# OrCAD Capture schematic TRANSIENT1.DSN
size A
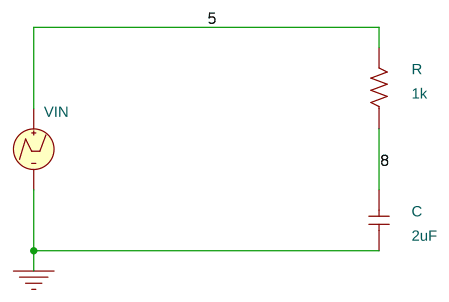
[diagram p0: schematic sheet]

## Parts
C  2uF  [RAD/CK05]
R  1k  [AX/RC05]
VIN  VPWL

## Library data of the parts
C = C
R = R
VIN = VPWL: PSpiceTemplate: V^@REFDES %+ %- ?DC|DC @DC| ?AC|AC @AC|\n+PWL @T1 @V1 @T2 @V2 #T3/@T3 @V3/ #T4/@T4 @V4/ #T5/@T5 @V5/ #T6/@T6 @V6/ #T7/@T7 @V7/ #T8/@T8 @V8/ #T9/@T9 @V9/ #T10/@T10 @V10/; T1: 0; T2: 1m; T3: 2m; T4: 3m; T5: 4m; T6: 5m; T7: 6m; V1: 0; V2: 1; V3: 0; V4: 1; V5: 0; V6: 1; V7: 0

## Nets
0: C.1 VIN.2(-)
5: R.2 VIN.1(+)
8: C.2 R.1
